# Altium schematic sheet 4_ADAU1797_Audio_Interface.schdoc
size 307 x 218 mm; Symbol: Drawing-Symbol_A4; Device: Drawing-Symbol_A4; @Project Name: Slowpoke; @Page Count: 7; @Update Date: 2025-12-13; @Create Date: 2025-12-13; @Schematic Name: Slowpoke_Sch; @Page No: 4; @Page Name: ADAU1797_Audio_Interface; Company: Analog Devices, Inc.; Version: V1.0; Page Size: A4; @Create Time: 06:28:30; @Update Time: 17:26:32; Width: 1170; Height: 825; Region Start: 1; X Region Count: 6; Y Region Count: 4; Blade Width: 10; Title Block Position: 3; @Board Name: Slowpoke
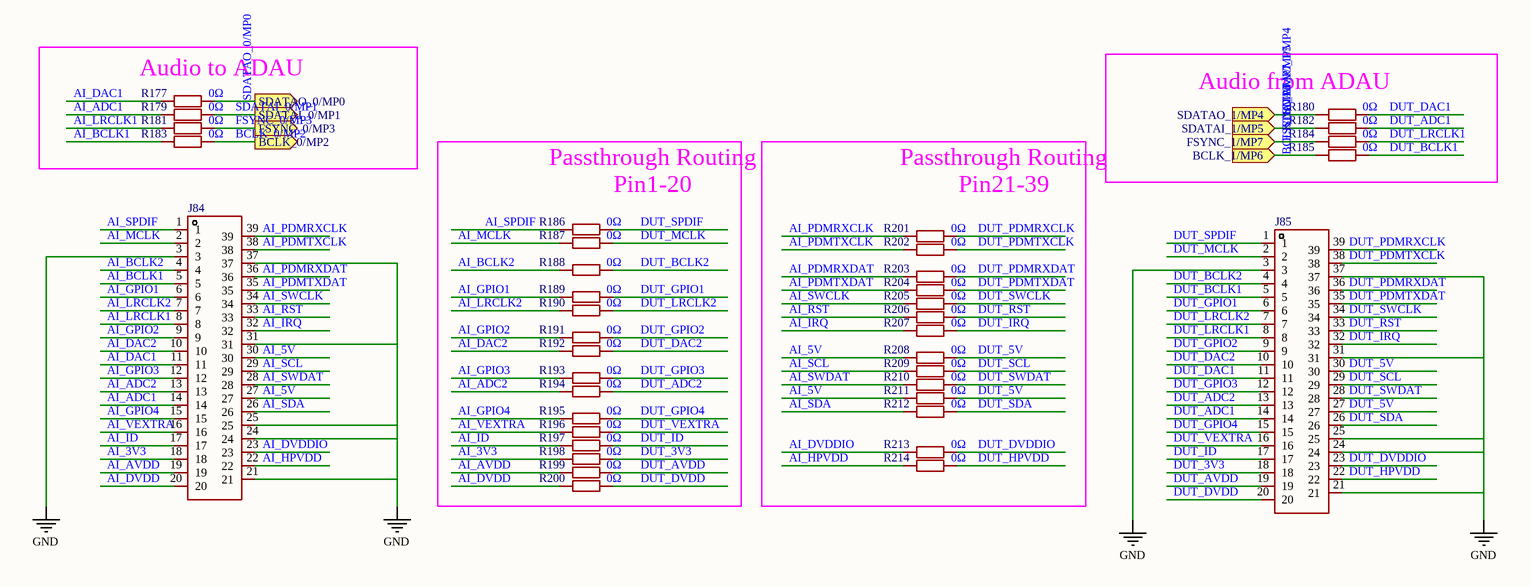
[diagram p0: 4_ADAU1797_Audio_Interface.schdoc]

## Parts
J84  TSW-113-08-G-T-RA  [HDR-TH_TSW-113-08-G-T-RA]  (value not drawn)
J85  TSW-113-08-G-T-RA  [HDR-TH_TSW-113-08-G-T-RA]  (value not drawn)
R177  0Ω  [R0603]
R179  0Ω  [R0603]
R180  0Ω  [R0603]
R181  0Ω  [R0603]
R182  0Ω  [R0603]
R183  0Ω  [R0603]
R184  0Ω  [R0603]
R185  0Ω  [R0603]
R186  0Ω  [R0603]
R187  0Ω  [R0603]
R188  0Ω  [R0603]
R189  0Ω  [R0603]
R190  0Ω  [R0603]
R191  0Ω  [R0603]
R192  0Ω  [R0603]
R193  0Ω  [R0603]
R194  0Ω  [R0603]
R195  0Ω  [R0603]
R196  0Ω  [R0603]
R197  0Ω  [R0603]
R198  0Ω  [R0603]
R199  0Ω  [R0603]
R200  0Ω  [R0603]
R201  0Ω  [R0603]
R202  0Ω  [R0603]
R203  0Ω  [R0603]
R204  0Ω  [R0603]
R205  0Ω  [R0603]
R206  0Ω  [R0603]
R207  0Ω  [R0603]
R208  0Ω  [R0603]
R209  0Ω  [R0603]
R210  0Ω  [R0603]
R211  0Ω  [R0603]
R212  0Ω  [R0603]
R213  0Ω  [R0603]
R214  0Ω  [R0603]

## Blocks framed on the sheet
Audio to ADAU: R177 R179 R181 R183
Audio from ADAU: R180 R182 R184 R185

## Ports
BCLK_0/MP2 (out), BCLK_1/MP6 (in), FSYNC_0/MP3 (out), FSYNC_1/MP7 (in), SDATAI_0/MP1 (out), SDATAI_1/MP5 (in), SDATAO_0/MP0 (out), SDATAO_1/MP4 (in)

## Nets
GND: J84.3 J84.21 J84.24 J84.25 J84.31 J84.37 J85.3 J85.21 J85.24 J85.25 J85.31 J85.37
AI_3V3: J84.18 R198.1
AI_5V: J84.27 J84.30 R208.1 R211.1
AI_ADC1: J84.14 R179.1
AI_ADC2: J84.13 R194.1
AI_AVDD: J84.19 R199.1
AI_BCLK1: J84.5 R183.1
AI_BCLK2: J84.4 R188.1
AI_DAC1: J84.11 R177.1
AI_DAC2: J84.10 R192.1
AI_DVDD: J84.20 R200.1
AI_DVDDIO: J84.23 R213.1
AI_GPIO1: J84.6 R189.1
AI_GPIO2: J84.9 R191.1
AI_GPIO3: J84.12 R193.1
AI_GPIO4: J84.15 R195.1
AI_HPVDD: J84.22 R214.1
AI_ID: J84.17 R197.1
AI_IRQ: J84.32 R207.1
AI_LRCLK1: J84.8 R181.1
AI_LRCLK2: J84.7 R190.1
AI_MCLK: J84.2 R187.1
AI_PDMRXCLK: J84.39 R201.1
AI_PDMRXDAT: J84.36 R203.1
AI_PDMTXCLK: J84.38 R202.1
AI_PDMTXDAT: J84.35 R204.1
AI_RST: J84.33 R206.1
AI_SCL: J84.29 R209.1
AI_SDA: J84.26 R212.1
AI_SPDIF: J84.1 R186.1
AI_SWCLK: J84.34 R205.1
AI_SWDAT: J84.28 R210.1
AI_VEXTRA: J84.16 R196.1
BCLK_0/MP2: R183.2 ; port BCLK_0/MP2
BCLK_1/MP6: R185.1 ; port BCLK_1/MP6
DUT_3V3: J85.18 R198.2
DUT_5V: J85.27 J85.30 R208.2 R211.2
DUT_ADC1: J85.14 R182.2
DUT_ADC2: J85.13 R194.2
DUT_AVDD: J85.19 R199.2
DUT_BCLK1: J85.5 R185.2
DUT_BCLK2: J85.4 R188.2
DUT_DAC1: J85.11 R180.2
DUT_DAC2: J85.10 R192.2
DUT_DVDD: J85.20 R200.2
DUT_DVDDIO: J85.23 R213.2
DUT_GPIO1: J85.6 R189.2
DUT_GPIO2: J85.9 R191.2
DUT_GPIO3: J85.12 R193.2
DUT_GPIO4: J85.15 R195.2
DUT_HPVDD: J85.22 R214.2
DUT_ID: J85.17 R197.2
DUT_IRQ: J85.32 R207.2
DUT_LRCLK1: J85.8 R184.2
DUT_LRCLK2: J85.7 R190.2
DUT_MCLK: J85.2 R187.2
DUT_PDMRXCLK: J85.39 R201.2
DUT_PDMRXDAT: J85.36 R203.2
DUT_PDMTXCLK: J85.38 R202.2
DUT_PDMTXDAT: J85.35 R204.2
DUT_RST: J85.33 R206.2
DUT_SCL: J85.29 R209.2
DUT_SDA: J85.26 R212.2
DUT_SPDIF: J85.1 R186.2
DUT_SWCLK: J85.34 R205.2
DUT_SWDAT: J85.28 R210.2
DUT_VEXTRA: J85.16 R196.2
FSYNC_0/MP3: R181.2 ; port FSYNC_0/MP3
FSYNC_1/MP7: R184.1 ; port FSYNC_1/MP7
SDATAI_0/MP1: R179.2 ; port SDATAI_0/MP1
SDATAI_1/MP5: R182.1 ; port SDATAI_1/MP5
SDATAO_0/MP0: R177.2 ; port SDATAO_0/MP0
SDATAO_1/MP4: R180.1 ; port SDATAO_1/MP4

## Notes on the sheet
- Passthrough Routing
  Pin1-20
- Passthrough Routing
  Pin21-39

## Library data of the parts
J84 J85 = TSW-113-08-G-T-RA: Manufacturer: SAMTEC; Add into BOM: yes; Pitch: 2.54mm
R177 R179-R214 = 0603WAF0000T5E: Manufacturer: UNI-ROYAL(厚声); Add into BOM: yes; Tolerance: ±1%; Power(Watts): 100mW; Voltage-Supply(Max): 75V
